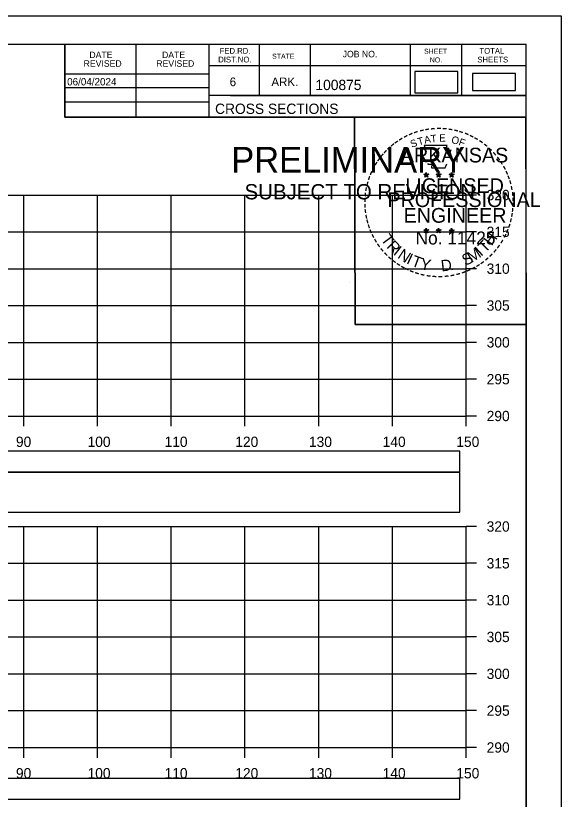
# Model space of a CAD drawing. Extents: x 1368122 to 1710785, y 373130 to 557566.
# Drawn here: x 1370777.8 to 1370851.9, y 373663.9 to 373770.3 of the extents above; entities that cross this region are included whole.
import ezdxf

# ---------------------------------------------------------------- set-up
doc = ezdxf.new("R2010")
doc.units = 0
for name, color, linetype in [('R_Axis', 7, 'Continuous'), ('R_Axis Annot', 7, 'Continuous'), ('R_Border', 7, 'Continuous'), ('R_Border PE', 7, 'Continuous'), ('R_Border Prem', 7, 'Continuous'), ('R_Drive', 7, 'Continuous'), ('R_Grid', 7, 'Continuous'), ('R_No Plot', 7, 'Continuous')]:
    doc.layers.add(name, color=color, linetype=linetype)

msp = doc.modelspace()

# ---------------------------------------------------------------- linework, layer by layer
for points in [[(1370539.77, 373708.4), (1370838.07, 373708.4), (1370838.07, 373711.21), (1370539.77, 373711.21)], [(1370539.77, 373702.93), (1370838.07, 373702.93), (1370838.07, 373708.34), (1370539.77, 373708.34)], [(1370539.77, 373663.98), (1370838.07, 373663.98), (1370838.07, 373666.79), (1370539.77, 373666.79)]]:
    msp.add_lwpolyline(points, close=True)
at = {"layer": 'R_Axis'}
for p, q in [((1370838.92, 373715.99), (1370838.92, 373745.99)), ((1370840.32, 373745.99), (1370838.92, 373745.99)), ((1370840.32, 373740.99), (1370838.92, 373740.99)), ((1370840.32, 373735.99), (1370838.92, 373735.99)), ((1370840.32, 373730.99), (1370838.92, 373730.99)), ((1370840.32, 373725.99), (1370838.92, 373725.99)), ((1370840.32, 373720.99), (1370838.92, 373720.99)), ((1370538.92, 373715.99), (1370838.92, 373715.99)), ((1370778.92, 373714.59), (1370778.92, 373715.99)), ((1370788.92, 373714.59), (1370788.92, 373715.99)), ((1370798.92, 373714.59), (1370798.92, 373715.99)), ((1370808.92, 373714.59), (1370808.92, 373715.99)), ((1370818.92, 373714.59), (1370818.92, 373715.99)), ((1370828.92, 373714.59), (1370828.92, 373715.99)), ((1370838.92, 373714.59), (1370838.92, 373715.99)), ((1370840.32, 373715.99), (1370838.92, 373715.99)), ((1370838.92, 373670.99), (1370838.92, 373700.99)), ((1370840.32, 373700.99), (1370838.92, 373700.99)), ((1370840.32, 373695.99), (1370838.92, 373695.99)), ((1370840.32, 373690.99), (1370838.92, 373690.99)), ((1370840.32, 373685.99), (1370838.92, 373685.99)), ((1370840.32, 373680.99), (1370838.92, 373680.99)), ((1370840.32, 373675.99), (1370838.92, 373675.99)), ((1370538.92, 373670.99), (1370838.92, 373670.99)), ((1370778.92, 373669.59), (1370778.92, 373670.99)), ((1370788.92, 373669.59), (1370788.92, 373670.99)), ((1370798.92, 373669.59), (1370798.92, 373670.99)), ((1370808.92, 373669.59), (1370808.92, 373670.99)), ((1370818.92, 373669.59), (1370818.92, 373670.99)), ((1370828.92, 373669.59), (1370828.92, 373670.99)), ((1370838.92, 373669.59), (1370838.92, 373670.99)), ((1370840.32, 373670.99), (1370838.92, 373670.99))]:
    msp.add_line(p, q, dxfattribs=at)
at = {"layer": 'R_Border'}
for p, q in [((1370530.92, 373766.45), (1370847.1, 373766.45)), ((1370784.46, 373756.57), (1370784.46, 373766.45)), ((1370794.14, 373756.57), (1370794.14, 373766.45)), ((1370804, 373766.45), (1370804, 373756.57)), ((1370810.84, 373766.45), (1370810.84, 373759.51)), ((1370817.78, 373766.45), (1370817.78, 373759.51)), ((1370831.36, 373766.45), (1370831.36, 373759.51)), ((1370838.3, 373766.45), (1370838.3, 373759.51)), ((1370847.1, 373560.99), (1370847.1, 373766.45)), ((1370847.1, 373763.51), (1370804, 373763.51)), ((1370847.1, 373763.53), (1370847.1, 373763.53)), ((1370784.46, 373762.43), (1370804, 373762.43)), ((1370784.46, 373760.57), (1370804, 373760.57)), ((1370847.1, 373759.51), (1370804, 373759.51)), ((1370806.96, 373759.51), (1370847.1, 373759.51)), ((1370784.46, 373758.63), (1370804, 373758.63)), ((1370847.1, 373756.57), (1370784.46, 373756.57))]:
    msp.add_line(p, q, dxfattribs=at)
at = {"layer": 'R_Border PE'}
for p, q in [((1370833.19, 373748.82), (1370833.53, 373748.71)), ((1370833.19, 373748.82), (1370833.44, 373748.78)), ((1370833.19, 373748.82), (1370833.42, 373748.7)), ((1370833.32, 373748.41), (1370833.53, 373748.71)), ((1370833.32, 373748.41), (1370833.44, 373748.66)), ((1370833.32, 373748.41), (1370833.53, 373748.63)), ((1370833.53, 373749.07), (1370833.49, 373748.82)), ((1370833.53, 373748.71), (1370833.53, 373749.07)), ((1370833.53, 373749.07), (1370833.58, 373748.82)), ((1370833.88, 373748.82), (1370833.53, 373748.71)), ((1370833.75, 373748.41), (1370833.53, 373748.71)), ((1370833.75, 373748.41), (1370833.53, 373748.63)), ((1370833.88, 373748.82), (1370833.6, 373748.77)), ((1370833.75, 373748.41), (1370833.61, 373748.7)), ((1370833.88, 373748.82), (1370833.68, 373748.72)), ((1370834.86, 373748.82), (1370835.2, 373748.71)), ((1370834.86, 373748.82), (1370835.11, 373748.78)), ((1370834.86, 373748.82), (1370835.09, 373748.7)), ((1370834.99, 373748.41), (1370835.2, 373748.71)), ((1370834.99, 373748.41), (1370835.11, 373748.66)), ((1370834.99, 373748.41), (1370835.2, 373748.63)), ((1370835.2, 373749.07), (1370835.16, 373748.82)), ((1370835.2, 373748.71), (1370835.2, 373749.07)), ((1370835.2, 373749.07), (1370835.25, 373748.82)), ((1370835.55, 373748.82), (1370835.2, 373748.71)), ((1370835.42, 373748.41), (1370835.2, 373748.71)), ((1370835.42, 373748.41), (1370835.2, 373748.63)), ((1370835.55, 373748.82), (1370835.27, 373748.77)), ((1370835.42, 373748.41), (1370835.28, 373748.7)), ((1370835.55, 373748.82), (1370835.35, 373748.72)), ((1370836.62, 373748.81), (1370836.97, 373748.7)), ((1370836.62, 373748.81), (1370836.87, 373748.76)), ((1370836.62, 373748.81), (1370836.86, 373748.69)), ((1370836.75, 373748.4), (1370836.97, 373748.7)), ((1370836.75, 373748.4), (1370836.88, 373748.64)), ((1370836.75, 373748.4), (1370836.97, 373748.62)), ((1370836.97, 373749.06), (1370836.93, 373748.81)), ((1370836.97, 373748.7), (1370836.97, 373749.06)), ((1370836.97, 373749.06), (1370837.02, 373748.81)), ((1370837.32, 373748.81), (1370836.97, 373748.7)), ((1370837.18, 373748.4), (1370836.97, 373748.7)), ((1370837.18, 373748.4), (1370836.97, 373748.61)), ((1370837.32, 373748.81), (1370837.03, 373748.76)), ((1370837.18, 373748.4), (1370837.04, 373748.69)), ((1370837.32, 373748.81), (1370837.11, 373748.71)), ((1370833.18, 373741.25), (1370833.53, 373741.14)), ((1370833.18, 373741.25), (1370833.43, 373741.2)), ((1370833.18, 373741.25), (1370833.42, 373741.13)), ((1370833.31, 373740.84), (1370833.53, 373741.14)), ((1370833.31, 373740.84), (1370833.44, 373741.08)), ((1370833.31, 373740.84), (1370833.53, 373741.06)), ((1370833.53, 373741.5), (1370833.49, 373741.25)), ((1370833.53, 373741.14), (1370833.53, 373741.5)), ((1370833.53, 373741.5), (1370833.58, 373741.25)), ((1370833.88, 373741.25), (1370833.53, 373741.14)), ((1370833.74, 373740.84), (1370833.53, 373741.14)), ((1370833.74, 373740.84), (1370833.53, 373741.05)), ((1370833.88, 373741.25), (1370833.59, 373741.2)), ((1370833.74, 373740.84), (1370833.61, 373741.13)), ((1370833.88, 373741.25), (1370833.67, 373741.15)), ((1370834.85, 373741.25), (1370835.2, 373741.14)), ((1370834.85, 373741.25), (1370835.1, 373741.2)), ((1370834.85, 373741.25), (1370835.09, 373741.13)), ((1370834.98, 373740.84), (1370835.2, 373741.14)), ((1370834.98, 373740.84), (1370835.11, 373741.08)), ((1370834.98, 373740.84), (1370835.2, 373741.06)), ((1370835.2, 373741.5), (1370835.16, 373741.25)), ((1370835.2, 373741.14), (1370835.2, 373741.5)), ((1370835.2, 373741.5), (1370835.25, 373741.25)), ((1370835.55, 373741.25), (1370835.2, 373741.14)), ((1370835.41, 373740.84), (1370835.2, 373741.14)), ((1370835.41, 373740.84), (1370835.2, 373741.05)), ((1370835.55, 373741.25), (1370835.26, 373741.2)), ((1370835.41, 373740.84), (1370835.28, 373741.13)), ((1370835.55, 373741.25), (1370835.34, 373741.15)), ((1370836.62, 373741.24), (1370836.97, 373741.13)), ((1370836.62, 373741.24), (1370836.87, 373741.19)), ((1370836.62, 373741.24), (1370836.85, 373741.12)), ((1370836.75, 373740.83), (1370836.97, 373741.13)), ((1370836.75, 373740.83), (1370836.88, 373741.07)), ((1370836.75, 373740.83), (1370836.96, 373741.05)), ((1370836.97, 373741.49), (1370836.93, 373741.24)), ((1370837.18, 373740.83), (1370836.96, 373741.04)), ((1370836.97, 373741.13), (1370836.97, 373741.49)), ((1370836.97, 373741.49), (1370837.02, 373741.24)), ((1370837.31, 373741.24), (1370836.97, 373741.13)), ((1370837.18, 373740.83), (1370836.97, 373741.13)), ((1370837.31, 373741.24), (1370837.03, 373741.19)), ((1370837.18, 373740.83), (1370837.04, 373741.12)), ((1370837.31, 373741.24), (1370837.11, 373741.14))]:
    msp.add_line(p, q, dxfattribs=at)
for points in [[(1370833.23, 373752.7), (1370833.5, 373751.87)], [(1370836.74, 373751.78), (1370836.88, 373752.06), (1370836.19, 373752.04), (1370836.34, 373752.7), (1370833.23, 373752.7)], [(1370833.72, 373750.28), (1370833.72, 373750.19), (1370834.28, 373750.17), (1370834.23, 373749.7), (1370836.1, 373749.7), (1370836.3, 373750.23)], [(1370833.53, 373749.07), (1370833.75, 373748.41), (1370833.19, 373748.82), (1370833.88, 373748.82), (1370833.32, 373748.41), (1370833.53, 373749.07)], [(1370835.2, 373749.07), (1370835.42, 373748.41), (1370834.86, 373748.82), (1370835.55, 373748.82), (1370834.99, 373748.41), (1370835.2, 373749.07)], [(1370836.97, 373749.06), (1370837.18, 373748.4), (1370836.62, 373748.81), (1370837.32, 373748.81), (1370836.75, 373748.4), (1370836.97, 373749.06)], [(1370833.53, 373741.5), (1370833.74, 373740.84), (1370833.18, 373741.25), (1370833.88, 373741.25), (1370833.31, 373740.84), (1370833.53, 373741.5)], [(1370835.2, 373741.5), (1370835.41, 373740.84), (1370834.85, 373741.25), (1370835.55, 373741.25), (1370834.98, 373740.84), (1370835.2, 373741.5)], [(1370836.97, 373741.49), (1370837.18, 373740.83), (1370836.62, 373741.24), (1370837.31, 373741.24), (1370836.75, 373740.83), (1370836.97, 373741.49)]]:
    msp.add_lwpolyline(points, dxfattribs=at)
for centre, radius in [((1370833.53, 373748.71), 0.172), ((1370833.53, 373748.71), 0.145), ((1370833.53, 373748.71), 0.116), ((1370833.53, 373748.71), 0.0991), ((1370833.53, 373748.71), 0.0747), ((1370833.53, 373748.71), 0.0495), ((1370833.53, 373748.71), 0.0296), ((1370835.2, 373748.71), 0.172), ((1370835.2, 373748.71), 0.145), ((1370835.2, 373748.71), 0.116), ((1370835.2, 373748.71), 0.0991), ((1370835.2, 373748.71), 0.0747), ((1370835.2, 373748.71), 0.0495), ((1370835.2, 373748.71), 0.0296), ((1370836.97, 373748.7), 0.172), ((1370836.97, 373748.7), 0.145), ((1370836.97, 373748.7), 0.116), ((1370836.97, 373748.7), 0.0991), ((1370836.97, 373748.7), 0.0747), ((1370836.97, 373748.7), 0.0495), ((1370836.97, 373748.7), 0.0296), ((1370833.53, 373741.14), 0.172), ((1370833.53, 373741.14), 0.145), ((1370833.53, 373741.14), 0.116), ((1370833.53, 373741.14), 0.0991), ((1370833.53, 373741.14), 0.0747), ((1370833.53, 373741.14), 0.0495), ((1370833.53, 373741.14), 0.0296), ((1370835.2, 373741.14), 0.172), ((1370835.2, 373741.14), 0.145), ((1370835.2, 373741.14), 0.116), ((1370835.2, 373741.14), 0.0991), ((1370835.2, 373741.14), 0.0747), ((1370835.2, 373741.14), 0.0495), ((1370835.2, 373741.14), 0.0296), ((1370836.97, 373741.13), 0.172), ((1370836.97, 373741.13), 0.145), ((1370836.97, 373741.13), 0.116), ((1370836.97, 373741.13), 0.0991), ((1370836.97, 373741.13), 0.0747), ((1370836.97, 373741.13), 0.0495), ((1370836.97, 373741.13), 0.0296)]:
    msp.add_circle(centre, radius, dxfattribs=at)
at = {"layer": 'R_Drive'}
for points in [[(1370831.97, 373759.86), (1370837.81, 373759.86), (1370837.81, 373762.78), (1370831.97, 373762.78)], [(1370839.78, 373760.16), (1370845.62, 373760.16), (1370845.62, 373762.47), (1370839.78, 373762.47)]]:
    msp.add_lwpolyline(points, close=True, dxfattribs=at)
at = {"layer": 'R_Grid'}
for p, q in [((1370538.92, 373745.99), (1370838.92, 373745.99)), ((1370778.92, 373715.99), (1370778.92, 373745.99)), ((1370788.92, 373715.99), (1370788.92, 373745.99)), ((1370798.92, 373715.99), (1370798.92, 373745.99)), ((1370808.92, 373715.99), (1370808.92, 373745.99)), ((1370818.92, 373715.99), (1370818.92, 373745.99)), ((1370828.92, 373715.99), (1370828.92, 373745.99)), ((1370838.92, 373715.99), (1370838.92, 373745.99)), ((1370538.92, 373740.99), (1370838.92, 373740.99)), ((1370538.92, 373735.99), (1370838.92, 373735.99)), ((1370538.92, 373730.99), (1370838.92, 373730.99)), ((1370538.92, 373725.99), (1370838.92, 373725.99)), ((1370538.92, 373720.99), (1370838.92, 373720.99)), ((1370538.92, 373715.99), (1370838.92, 373715.99)), ((1370538.92, 373700.99), (1370838.92, 373700.99)), ((1370778.92, 373670.99), (1370778.92, 373700.99)), ((1370788.92, 373670.99), (1370788.92, 373700.99)), ((1370798.92, 373670.99), (1370798.92, 373700.99)), ((1370808.92, 373670.99), (1370808.92, 373700.99)), ((1370818.92, 373670.99), (1370818.92, 373700.99)), ((1370828.92, 373670.99), (1370828.92, 373700.99)), ((1370838.92, 373670.99), (1370838.92, 373700.99)), ((1370538.92, 373695.99), (1370838.92, 373695.99)), ((1370538.92, 373690.99), (1370838.92, 373690.99)), ((1370538.92, 373685.99), (1370838.92, 373685.99)), ((1370538.92, 373680.99), (1370838.92, 373680.99)), ((1370538.92, 373675.99), (1370838.92, 373675.99)), ((1370538.92, 373670.99), (1370838.92, 373670.99))]:
    msp.add_line(p, q, dxfattribs=at)
at = {"layer": 'R_No Plot'}
for p, q in [((1370518.52, 373770.34), (1370851.85, 373770.34)), ((1370823.13, 373734.11), (1370823.13, 373734.11))]:
    msp.add_line(p, q, dxfattribs=at)
for points in [[(1370518.51, 373770.34), (1370851.85, 373770.34), (1370851.85, 373557), (1370518.51, 373557)], [(1370764.84, 373766.45), (1370784.46, 373766.45), (1370784.46, 373756.57), (1370800.57, 373756.57), (1370823.77, 373756.57), (1370823.89, 373728.41), (1370847.1, 373728.41), (1370847.1, 373560.99), (1370530.92, 373560.99), (1370530.92, 373766.45)], [(1370823.77, 373756.57), (1370846.98, 373756.57), (1370847.1, 373728.41), (1370823.89, 373728.41)]]:
    msp.add_lwpolyline(points, close=True, dxfattribs=at)

# ---------------------------------------------------------------- texts
at = {"layer": 'R_Axis Annot'}
for s, p in [('320', (1370841.72, 373745.29)), ('315', (1370841.72, 373740.29)), ('310', (1370841.72, 373735.29)), ('305', (1370841.72, 373730.29)), ('300', (1370841.72, 373725.29)), ('295', (1370841.72, 373720.29)), ('290', (1370841.72, 373715.29)), ('90', (1370777.83, 373711.79)), ('100', (1370787.55, 373711.79)), ('110', (1370798, 373711.79)), ('120', (1370807.6, 373711.79)), ('130', (1370817.6, 373711.79)), ('140', (1370827.6, 373711.79)), ('150', (1370837.6, 373711.79)), ('320', (1370841.72, 373700.29)), ('315', (1370841.72, 373695.29)), ('310', (1370841.72, 373690.29)), ('305', (1370841.72, 373685.29)), ('300', (1370841.72, 373680.29)), ('295', (1370841.72, 373675.29)), ('290', (1370841.72, 373670.29)), ('90', (1370777.83, 373666.79)), ('100', (1370787.55, 373666.79)), ('110', (1370798, 373666.79)), ('120', (1370807.6, 373666.79)), ('130', (1370817.6, 373666.79)), ('140', (1370827.6, 373666.79)), ('150', (1370837.6, 373666.79))]:
    msp.add_text(s, height=1.4, dxfattribs=at).set_placement(p)
at = {"layer": 'R_Border'}
for s, height, p in [('DATE', 0.879, (1370787.8, 373764.58)), ('DATE', 0.879, (1370797.66, 373764.58)), ('FED.RD.', 0.782, (1370805.48, 373765.17)), ('STATE', 0.684, (1370812.6, 373764.49)), ('JOB NO.', 0.879, (1370822.18, 373764.69)), ('SHEET', 0.684, (1370833.22, 373765.17)), ('TOTAL', 0.782, (1370840.74, 373765.17)), ('REVISED', 0.879, (1370787.02, 373763.4)), ('REVISED', 0.879, (1370796.88, 373763.4)), ('DIST.NO.', 0.782, (1370805.28, 373763.99)), ('NO.', 0.684, (1370834, 373763.99)), ('SHEETS', 0.782, (1370840.46, 373763.99)), ('6', 1.17, (1370806.84, 373760.77)), ('ARK.', 1.172, (1370812.5, 373760.77)), ('100875', 1.4, (1370818.48, 373760.24)), ('CROSS SECTIONS', 1.4, (1370804.86, 373757))]:
    msp.add_text(s, height=height, rotation=360, dxfattribs=at).set_placement(p)
msp.add_text('06/04/2024', height=1, dxfattribs=at).set_placement((1370784.78, 373760.87))
at = {"layer": 'R_Border PE'}
for s, height, rotation, p in [('-', 1.6, 19.1761, (1370831.97, 373753.83)), ('-', 1.6, 13.6301, (1370832.72, 373754.07)), ('-', 1.6, 10.2193, (1370833.4, 373754.23)), ('-', 1.6, 5.8968, (1370834.13, 373754.34)), ('-', 1.6, 0.1862, (1370834.9, 373754.41)), ('-', 1.6, 357.743, (1370835.63, 373754.4)), ('-', 1.6, 352.1617, (1370836.37, 373754.34)), ('-', 1.6, 347.2049, (1370837.09, 373754.23)), ('-', 1.6, 342.3362, (1370837.72, 373754.07)), ('-', 1.6, 34.0636, (1370830.11, 373752.87)), ('-', 1.6, 28.7918, (1370830.71, 373753.24)), ('-', 1.6, 24.3072, (1370831.34, 373753.56)), ('S', 1, 21.594, (1370831.58, 373752.38)), ('T', 1, 16.4036, (1370832.5, 373752.71)), ('A', 1, 11.2132, (1370833.32, 373752.96)), ('T', 1, 6.0228, (1370834.17, 373753.12)), ('E', 1, 0.8323, (1370835.28, 373753.23)), ('O', 1, 350.4515, (1370836.88, 373753.02)), ('F', 1, 340.0707, (1370837.83, 373752.8)), ('-', 1.6, 337.8551, (1370838.46, 373753.85)), ('-', 1.6, 334.1211, (1370839.09, 373753.58)), ('-', 1.6, 329.6409, (1370839.67, 373753.3)), ('-', 1.6, 325.8627, (1370840.31, 373752.93)), ('-', 1.6, 42.9622, (1370828.62, 373751.68)), ('-', 1.6, 38.9507, (1370829.06, 373752.1)), ('-', 1.6, 36.2317, (1370829.53, 373752.47)), ('ARKANSAS', 2, 360, (1370830.08, 373750.41)), ('-', 1.6, 320.5297, (1370840.92, 373752.51)), ('-', 1.6, 315.5786, (1370841.52, 373752.02)), ('-', 1.6, 50.6142, (1370827.77, 373750.72)), ('-', 1.6, 48.423, (1370828.18, 373751.2)), ('-', 1.6, 309.8797, (1370842.09, 373751.47)), ('-', 1.6, 58.0706, (1370827.03, 373749.62)), ('-', 1.6, 54.2325, (1370827.36, 373750.15)), ('-', 1.6, 306.6522, (1370842.62, 373750.87)), ('-', 1.4, 303.6753, (1370843.1, 373750.3)), ('-', 1.6, 67.7743, (1370826.46, 373748.4)), ('-', 1.6, 62.8713, (1370826.72, 373749.01)), ('-', 1.6, 299.6684, (1370843.42, 373749.69)), ('-', 1.6, 294.6628, (1370843.74, 373749.08)), ('-', 1.6, 72.3945, (1370826.24, 373747.77)), ('LICENSED', 2, 360, (1370830.68, 373746.26)), ('DWB', 0.01, 360, (1370833.52, 373748.7)), ('DWB', 0.01, 360, (1370835.19, 373748.7)), ('DWB', 0.01, 360, (1370836.96, 373748.69)), ('-', 1.6, 290.5728, (1370844, 373748.5)), ('-', 1.6, 81.2013, (1370825.91, 373746.34)), ('-', 1.6, 75.461, (1370826.05, 373747.05)), ('-', 1.6, 285.1233, (1370844.24, 373747.92)), ('-', 1.6, 280.5493, (1370844.44, 373747.18)), ('-', 1.6, 85.1863, (1370825.84, 373745.65)), ('PROFESSIONAL', 2, 360, (1370828.25, 373744.36)), ('-', 1.6, 276.5962, (1370844.6, 373746.41)), ('-', 1.6, 89.0622, (1370825.81, 373744.95)), ('-', 1.6, 274.3301, (1370844.66, 373745.69)), ('-', 1.6, 269.9407, (1370844.69, 373745.06)), ('-', 1.6, 94.1959, (1370825.85, 373744.22)), ('-', 1.6, 98.9479, (1370825.92, 373743.56)), ('ENGINEER', 2, 360, (1370830.44, 373742.23)), ('-', 1.6, 263.5172, (1370844.67, 373744.39)), ('-', 1.6, 101.7149, (1370826.06, 373742.82)), ('-', 1.6, 255.7626, (1370844.49, 373743.06)), ('-', 1.6, 260.9953, (1370844.6, 373743.74)), ('-', 1.6, 105.4578, (1370826.22, 373742.23)), ('-', 1.6, 109.0874, (1370826.43, 373741.6)), ('-', 1.6, 252.8681, (1370844.31, 373742.34)), ('-', 1.6, 114.0643, (1370826.69, 373741)), ('-', 1.6, 115.7289, (1370826.99, 373740.38)), ('T', 1.54, 306.0406, (1370827.29, 373739.97)), ('No. 11425', 1.757, 360, (1370832.07, 373739.28)), ('DWB', 0.01, 360, (1370833.52, 373741.13)), ('DWB', 0.01, 360, (1370835.19, 373741.13)), ('DWB', 0.01, 360, (1370836.95, 373741.12)), ('H', 1.54, 54.6088, (1370842.41, 373739.01)), ('-', 1.6, 244.6197, (1370843.83, 373741.04)), ('-', 1.6, 247.8887, (1370844.09, 373741.67)), ('-', 1.6, 120.4471, (1370827.35, 373739.8)), ('R', 1.54, 314.005, (1370828.05, 373738.93)), ('T', 1.54, 46.6444, (1370841.52, 373738.07)), ('-', 1.6, 239.0712, (1370843.43, 373740.29)), ('-', 1.6, 125.8934, (1370827.75, 373739.24)), ('-', 1.6, 130.7181, (1370828.21, 373738.68)), ('I', 1.54, 321.9694, (1370828.95, 373737.99)), ('N', 1.54, 326.5002, (1370829.52, 373737.52)), ('M', 1.54, 32.6563, (1370839.67, 373736.74)), ('I', 1.54, 42.1136, (1370840.96, 373737.59)), ('-', 1.6, 231.2538, (1370842.6, 373739.07)), ('-', 1.6, 233.8452, (1370843.03, 373739.64)), ('-', 1.6, 134.2238, (1370828.73, 373738.14)), ('-', 1.6, 138.9338, (1370829.26, 373737.67)), ('I', 1.54, 335.3603, (1370830.73, 373736.74)), ('T', 1.54, 339.8912, (1370831.39, 373736.41)), ('Y', 1.54, 347.8556, (1370832.61, 373735.96)), ('S', 1.54, 26.9312, (1370838.84, 373736.34)), ('-', 1.6, 221.0851, (1370841.6, 373738)), ('-', 1.6, 225.7653, (1370842.12, 373738.51)), ('-', 1.6, 144.6463, (1370829.81, 373737.27)), ('-', 1.6, 148.0898, (1370830.37, 373736.9)), ('-', 1.6, 151.5704, (1370830.95, 373736.57)), ('D', 1.54, 6.3969, (1370835.59, 373735.61)), ('-', 1.6, 212.2491, (1370840.52, 373737.14)), ('-', 1.6, 215.7363, (1370841.05, 373737.52)), ('-', 1.6, 154.6002, (1370831.47, 373736.33)), ('-', 1.6, 158.5612, (1370832.1, 373736.07)), ('-', 1.6, 162.7983, (1370832.78, 373735.86)), ('.', 1.54, 13.7642, (1370836.78, 373735.73)), ('-', 1.6, 195.4743, (1370838.04, 373735.96)), ('-', 1.6, 200.7184, (1370838.71, 373736.2)), ('-', 1.6, 204.2516, (1370839.33, 373736.47)), ('-', 1.6, 207.3568, (1370839.96, 373736.79)), ('-', 1.6, 167.5555, (1370833.5, 373735.69)), ('-', 1.6, 173.1155, (1370834.27, 373735.58)), ('-', 1.6, 176.5183, (1370835.02, 373735.53)), ('-', 1.6, 181.5918, (1370835.76, 373735.55)), ('-', 1.6, 185.8167, (1370836.57, 373735.63)), ('-', 1.6, 191.2858, (1370837.31, 373735.76))]:
    msp.add_text(s, height=height, rotation=rotation, dxfattribs=at).set_placement(p)
at = {"layer": 'R_Border Prem'}
for s, height, p in [('PRELIMINARY', 3.5, (1370807.05, 373749.03)), ('DWB', 0.01, (1370807.8, 373750.88)), ('SUBJECT TO REVISION', 2.0751, (1370808.86, 373745.4))]:
    msp.add_text(s, height=height, rotation=360, dxfattribs=at).set_placement(p)

doc.saveas('drawing.dxf')
